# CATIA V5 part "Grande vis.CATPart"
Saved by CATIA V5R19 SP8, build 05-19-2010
Part number: vis ski-glissière grand
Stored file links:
  G:\EU_thinkMotion\CFAO_2010\MMS_groupe2\MMS_groupe2\A reprendre\rbouchet\rbouchet_Catia\Grande vis.CATPart

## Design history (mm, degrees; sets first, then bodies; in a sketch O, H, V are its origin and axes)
Body1 (main body)
  Sketch1 on yz-plane, origin (0, 0, 0), H (0, 1, 0), V (0, 0, 1)
    line L1 (0, 37) -> (3.5, 37)
    point P1 (0, 37)
    line L2 (3.5, 37) -> (3.5, 32)
    line L3 (3.5, 32) -> (3, 32)
    line L4 (3, 32) -> (3, 0)
    line L5 (3, 0) -> (0, 0)
    point P6 (0, 0)
    length L1 = 3.5
    length L4 = 32
    length L2 = 5
    length L3 = 0.5
    distance L5 H = 0
    coincidence: P1 V, P6 V
    horizontal: L1 H, L3 H, L5 H
    vertical: L2 V, L4 V
  Shaft1: profile Sketch1, axis Sketch1.V, angle 360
